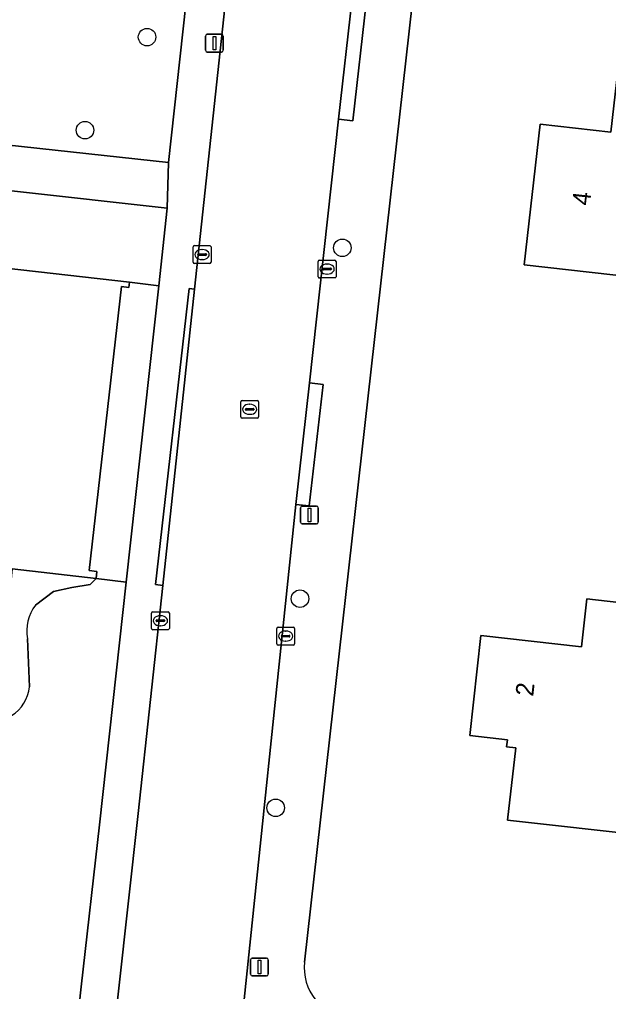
# Model space of a CAD drawing. Extents: x 162184 to 163154, y 385507 to 386516.
# Drawn here: x 162297.1 to 162330, y 385900.6 to 385954.9 of the extents above; entities that cross this region are included whole.
import ezdxf

# ---------------------------------------------------------------- set-up
doc = ezdxf.new("R2010")
doc.units = 0
for name, color, linetype in [('IMGEO_Boom', 7, 'Continuous'), ('IMGEO_Erf', 7, 'Continuous'), ('IMGEO_Groenvoorziening', 7, 'Continuous'), ('IMGEO_Kolk', 7, 'Continuous'), ('IMGEO_Lichtmast', 7, 'Continuous'), ('IMGEO_Pand', 7, 'Continuous'), ('IMGEO_Pand_nummerreeks', 7, 'Continuous'), ('IMGEO_Rijbaan_lokaal_open', 7, 'Continuous'), ('IMGEO_Rioolput', 7, 'Continuous'), ('IMGEO_Voetpad_open', 7, 'Continuous')]:
    doc.layers.add(name, color=color, linetype=linetype)

msp = doc.modelspace()

# ---------------------------------------------------------------- linework, layer by layer
at = {"layer": 'IMGEO_Boom'}
for centre in [(162304.242, 385953.933), (162300.775, 385948.732), (162315.151, 385942.163), (162312.782, 385922.559), (162311.424, 385910.875)]:
    msp.add_circle(centre, 0.489, dxfattribs=at)
at = {"layer": 'IMGEO_Erf'}
msp.add_lwpolyline([(162328.975, 386043.984), (162324.028, 386000), (162313.036, 385902.247)], dxfattribs=at)
for points in [[(162341.386, 385949.331), (162336.906, 385949.839), (162336.451, 385945.838), (162335.79, 385940.016), (162330.265, 385940.644), (162325.296, 385941.208), (162326.189, 385949.065), (162330.142, 385948.616), (162330.792, 385954.341), (162335.761, 385953.777), (162341.813, 385953.089)], [(162338.284, 385931.993), (162337.602, 385925.852), (162334.596, 385926.197), (162333.253, 385914.201), (162332.776, 385914.255), (162332.223, 385909.314), (162324.378, 385910.191), (162324.83, 385914.225), (162324.326, 385914.281), (162324.371, 385914.682), (162322.264, 385914.918), (162322.889, 385920.507), (162328.511, 385919.878), (162328.809, 385922.544), (162330.592, 385922.345), (162331.798, 385932.685)]]:
    msp.add_lwpolyline(points, close=True, dxfattribs=at)
msp.add_arc((162315.865, 385901.93), 2.846, 173.6034, 263.6318, dxfattribs=at)
at = {"layer": 'IMGEO_Groenvoorziening'}
for points in [[(162287.293, 385948.899), (162305.445, 385946.92), (162308.336, 385973.43)], [(162298.011, 385922.193), (162299.009, 385922.952), (162300.039, 385923.181), (162301.055, 385923.347), (162301.395, 385923.695), (162296.7, 385924.228), (162296.135, 385918.103), (162285.746, 385919.171), (162281.216, 385919.685), (162280.994, 385917.729), (162283.394, 385917.48), (162284.595, 385917.841), (162286.256, 385917.978), (162288.664, 385917.633), (162290.709, 385917.246), (162292.811, 385916.527), (162294.784, 385915.888)], [(162301.577, 385909.923), (162303.065, 385923.488), (162301.395, 385923.695), (162301.055, 385923.347), (162300.039, 385923.181), (162299.009, 385922.952), (162298.011, 385922.193)], [(162297.666, 385917.642), (162297.57, 385920.323)], [(162297.57, 385920.323), (162297.666, 385917.642)], [(162275.621, 385897.854), (162297.198, 385895.455), (162297.469, 385895.462), (162297.738, 385895.492), (162298.003, 385895.547), (162298.262, 385895.625), (162298.513, 385895.726), (162298.754, 385895.849), (162298.983, 385895.993), (162299.199, 385896.157), (162299.399, 385896.339), (162299.582, 385896.539), (162299.746, 385896.754), (162299.89, 385896.983), (162300.014, 385897.224), (162300.115, 385897.475), (162300.193, 385897.734), (162300.243, 385897.966), (162300.567, 385900.867), (162301.577, 385909.923)]]:
    msp.add_lwpolyline(points, dxfattribs=at)
msp.add_lwpolyline([(162296.364, 385941.021), (162303.254, 385940.239), (162304.896, 385940.036), (162305.369, 385944.374), (162288.289, 385946.274), (162287.788, 385941.99)], close=True, dxfattribs=at)
for centre, radius, start, end in [((162299.849, 385920.772), 2.323, 142.3043, 191.1566), ((162299.849, 385920.772), 2.323, 142.3043, 191.1566), ((162295.59, 385917.809), 2.083, 247.2373, 355.4125), ((162295.59, 385917.809), 2.083, 247.2373, 355.4125)]:
    msp.add_arc(centre, radius, start, end, dxfattribs=at)
at = {"layer": 'IMGEO_Kolk'}
for p, q in [((162306.813, 385941.356), (162306.813, 385942.208)), ((162306.888, 385942.282), (162307.74, 385942.282)), ((162307.301, 385942.062), (162307.326, 385942.062)), ((162307.814, 385942.208), (162307.814, 385941.356)), ((162307.072, 385941.776), (162307.072, 385941.788)), ((162307.51, 385941.739), (162307.112, 385941.739)), ((162307.115, 385941.825), (162307.513, 385941.825)), ((162307.324, 385941.502), (162307.299, 385941.502)), ((162307.556, 385941.788), (162307.556, 385941.776)), ((162313.87, 385941.475), (162314.722, 385941.475)), ((162307.74, 385941.282), (162306.888, 385941.282)), ((162313.795, 385940.549), (162313.795, 385941.401)), ((162314.054, 385940.969), (162314.054, 385940.981)), ((162314.492, 385940.932), (162314.094, 385940.932)), ((162314.097, 385941.018), (162314.495, 385941.018)), ((162314.283, 385941.255), (162314.308, 385941.255)), ((162314.538, 385940.981), (162314.538, 385940.969)), ((162314.796, 385941.401), (162314.796, 385940.549)), ((162314.722, 385940.475), (162313.87, 385940.475)), ((162314.306, 385940.695), (162314.281, 385940.695)), ((162304.485, 385920.902), (162304.485, 385921.754)), ((162304.56, 385921.828), (162305.412, 385921.828)), ((162304.744, 385921.322), (162304.744, 385921.334)), ((162304.787, 385921.371), (162305.185, 385921.371)), ((162304.973, 385921.608), (162304.998, 385921.608)), ((162305.228, 385921.334), (162305.228, 385921.322)), ((162305.486, 385921.754), (162305.486, 385920.902)), ((162305.412, 385920.828), (162304.56, 385920.828)), ((162305.182, 385921.285), (162304.784, 385921.285)), ((162304.996, 385921.048), (162304.971, 385921.048)), ((162311.48, 385920.041), (162311.48, 385920.893)), ((162311.555, 385920.967), (162312.407, 385920.967)), ((162312.481, 385920.893), (162312.481, 385920.041)), ((162311.739, 385920.461), (162311.739, 385920.473)), ((162312.177, 385920.424), (162311.779, 385920.424)), ((162311.782, 385920.51), (162312.18, 385920.51)), ((162311.968, 385920.747), (162311.993, 385920.747)), ((162312.223, 385920.473), (162312.223, 385920.461)), ((162312.407, 385919.967), (162311.555, 385919.967)), ((162311.991, 385920.187), (162311.966, 385920.187))]:
    msp.add_line(p, q, dxfattribs=at)
for points in [[(162306.813, 385941.356), (162306.813, 385942.208)], [(162306.888, 385942.282), (162307.74, 385942.282)], [(162307.814, 385942.208), (162307.814, 385941.356)], [(162313.87, 385941.475), (162314.722, 385941.475)], [(162307.74, 385941.282), (162306.888, 385941.282)], [(162313.795, 385940.549), (162313.795, 385941.401)], [(162314.796, 385941.401), (162314.796, 385940.549)], [(162314.722, 385940.475), (162313.87, 385940.475)], [(162304.485, 385920.902), (162304.485, 385921.754)], [(162304.56, 385921.828), (162305.412, 385921.828)], [(162305.486, 385921.754), (162305.486, 385920.902)], [(162305.412, 385920.828), (162304.56, 385920.828)], [(162311.48, 385920.041), (162311.48, 385920.893)], [(162311.555, 385920.967), (162312.407, 385920.967)], [(162312.481, 385920.893), (162312.481, 385920.041)], [(162312.407, 385919.967), (162311.555, 385919.967)]]:
    msp.add_lwpolyline(points, dxfattribs=at)
for centre, radius, start, end in [((162306.89, 385942.206), 0.0765, 91.552, 178.448), ((162306.89, 385942.206), 0.0765, 91.552, 178.448), ((162307.738, 385942.206), 0.0765, 1.552, 88.448), ((162307.738, 385942.206), 0.0765, 1.552, 88.448), ((162307.112, 385941.785), 0.0403, 85.8775, 175.7526), ((162307.109, 385941.775), 0.0366, 178.938, 274.7102), ((162307.513, 385941.782), 0.043, 264.8664, 352.4533), ((162307.517, 385941.787), 0.0386, 1.7309, 96.639), ((162313.872, 385941.399), 0.0765, 91.552, 178.448), ((162313.872, 385941.399), 0.0765, 91.552, 178.448), ((162314.72, 385941.399), 0.0765, 1.552, 88.448), ((162314.72, 385941.399), 0.0765, 1.552, 88.448), ((162306.89, 385941.358), 0.0765, 181.552, 268.448), ((162306.89, 385941.358), 0.0765, 181.552, 268.448), ((162307.738, 385941.358), 0.0765, 271.552, 358.448), ((162307.738, 385941.358), 0.0765, 271.552, 358.448), ((162314.094, 385940.978), 0.0403, 85.8775, 175.7526), ((162314.091, 385940.968), 0.0366, 178.938, 274.7102), ((162314.495, 385940.975), 0.043, 264.8664, 352.4533), ((162314.499, 385940.98), 0.0386, 1.7309, 96.639), ((162313.872, 385940.551), 0.0765, 181.552, 268.448), ((162313.872, 385940.551), 0.0765, 181.552, 268.448), ((162314.72, 385940.551), 0.0765, 271.552, 358.448), ((162314.72, 385940.551), 0.0765, 271.552, 358.448), ((162304.562, 385921.752), 0.0765, 91.552, 178.448), ((162304.562, 385921.752), 0.0765, 91.552, 178.448), ((162304.784, 385921.331), 0.0403, 85.8775, 175.7526), ((162305.189, 385921.333), 0.0386, 1.7309, 96.639), ((162305.41, 385921.752), 0.0765, 1.552, 88.448), ((162305.41, 385921.752), 0.0765, 1.552, 88.448), ((162304.562, 385920.904), 0.0765, 181.552, 268.448), ((162304.562, 385920.904), 0.0765, 181.552, 268.448), ((162304.781, 385921.321), 0.0366, 178.938, 274.7102), ((162305.185, 385921.328), 0.043, 264.8664, 352.4533), ((162305.41, 385920.904), 0.0765, 271.552, 358.448), ((162305.41, 385920.904), 0.0765, 271.552, 358.448), ((162311.557, 385920.891), 0.0765, 91.552, 178.448), ((162311.557, 385920.891), 0.0765, 91.552, 178.448), ((162312.405, 385920.891), 0.0765, 1.552, 88.448), ((162312.405, 385920.891), 0.0765, 1.552, 88.448), ((162311.779, 385920.47), 0.0403, 85.8775, 175.7526), ((162311.776, 385920.46), 0.0366, 178.938, 274.7102), ((162312.18, 385920.467), 0.043, 264.8664, 352.4533), ((162312.184, 385920.472), 0.0386, 1.7309, 96.639), ((162311.557, 385920.043), 0.0765, 181.552, 268.448), ((162311.557, 385920.043), 0.0765, 181.552, 268.448), ((162312.405, 385920.043), 0.0765, 271.552, 358.448), ((162312.405, 385920.043), 0.0765, 271.552, 358.448)]:
    msp.add_arc(centre, radius, start, end, dxfattribs=at)
for centre, major_axis, ratio, start_param, end_param in [((162307.3, 385941.782), (-0.387, 0.002), 0.722429, 4.712389, 7.853982), ((162307.325, 385941.782), (-0.39, 0.002), 0.717154, 1.570796, 4.712389), ((162314.282, 385940.975), (-0.387, 0.002), 0.722429, 4.712389, 7.853982), ((162314.307, 385940.975), (-0.39, 0.002), 0.717154, 1.570796, 4.712389), ((162304.972, 385921.328), (-0.387, 0.002), 0.722429, 4.712389, 7.853982), ((162304.997, 385921.328), (-0.39, 0.002), 0.717154, 1.570796, 4.712389), ((162311.967, 385920.467), (-0.387, 0.002), 0.722429, 4.712389, 7.853982), ((162311.992, 385920.467), (-0.39, 0.002), 0.717154, 1.570796, 4.712389)]:
    msp.add_ellipse(centre, major_axis=major_axis, ratio=ratio, start_param=start_param, end_param=end_param, dxfattribs=at)
at = {"layer": 'IMGEO_Lichtmast'}
for p, q in [((162307.506, 385953.194), (162307.506, 385953.994)), ((162307.506, 385953.994), (162307.506, 385953.194)), ((162307.606, 385954.094), (162308.396, 385954.094)), ((162308.396, 385954.094), (162307.606, 385954.094)), ((162308.496, 385953.994), (162308.496, 385953.194)), ((162308.496, 385953.194), (162308.496, 385953.994)), ((162308.396, 385953.094), (162307.606, 385953.094)), ((162307.606, 385953.094), (162308.396, 385953.094)), ((162312.81, 385926.833), (162312.81, 385927.633)), ((162312.81, 385927.633), (162312.81, 385926.833)), ((162312.91, 385927.733), (162313.7, 385927.733)), ((162313.7, 385927.733), (162312.91, 385927.733)), ((162313.8, 385927.633), (162313.8, 385926.833)), ((162313.8, 385926.833), (162313.8, 385927.633)), ((162313.7, 385926.733), (162312.91, 385926.733)), ((162312.91, 385926.733), (162313.7, 385926.733)), ((162310.019, 385901.583), (162310.019, 385902.383)), ((162310.019, 385902.383), (162310.019, 385901.583)), ((162310.119, 385902.483), (162310.909, 385902.483)), ((162310.909, 385902.483), (162310.119, 385902.483)), ((162311.009, 385902.383), (162311.009, 385901.583)), ((162311.009, 385901.583), (162311.009, 385902.383)), ((162310.909, 385901.483), (162310.119, 385901.483)), ((162310.119, 385901.483), (162310.909, 385901.483))]:
    msp.add_line(p, q, dxfattribs=at)
for points in [[(162307.926, 385953.969), (162308.076, 385953.969), (162308.076, 385953.219), (162307.926, 385953.219), (162307.926, 385953.969)], [(162313.23, 385927.608), (162313.38, 385927.608), (162313.38, 385926.858), (162313.23, 385926.858), (162313.23, 385927.608)], [(162310.439, 385902.358), (162310.589, 385902.358), (162310.589, 385901.608), (162310.439, 385901.608), (162310.439, 385902.358)]]:
    msp.add_lwpolyline(points, dxfattribs=at)
for centre, start, end in [((162307.606, 385953.994), 90, 180), ((162307.606, 385953.994), 90, 180), ((162308.396, 385953.994), 0, 90), ((162308.396, 385953.994), 360, 90), ((162307.606, 385953.194), 180, 270), ((162307.606, 385953.194), 180, 270), ((162308.396, 385953.194), 270, 0), ((162308.396, 385953.194), 270, 0), ((162312.91, 385927.633), 90, 180), ((162312.91, 385927.633), 90, 180), ((162313.7, 385927.633), 0, 90), ((162313.7, 385927.633), 360, 90), ((162312.91, 385926.833), 180, 270), ((162312.91, 385926.833), 180, 270), ((162313.7, 385926.833), 270, 0), ((162313.7, 385926.833), 270, 0), ((162310.119, 385902.383), 90, 180), ((162310.119, 385902.383), 90, 180), ((162310.909, 385902.383), 0, 90), ((162310.909, 385902.383), 360, 90), ((162310.119, 385901.583), 180, 270), ((162310.119, 385901.583), 180, 270), ((162310.909, 385901.583), 270, 0), ((162310.909, 385901.583), 270, 0)]:
    msp.add_arc(centre, 0.1, start, end, dxfattribs=at)
at = {"layer": 'IMGEO_Pand'}
for points in [[(162336.906, 385949.839), (162341.386, 385949.331), (162341.813, 385953.089), (162335.761, 385953.777), (162330.792, 385954.341), (162330.142, 385948.616), (162326.189, 385949.065), (162325.296, 385941.208), (162330.265, 385940.644), (162335.79, 385940.016), (162336.451, 385945.838)], [(162296.364, 385941.021), (162296.04, 385938.627), (162295.384, 385932.873), (162294.432, 385924.485), (162296.7, 385924.228), (162301.395, 385923.695), (162301.439, 385924.078), (162301.007, 385924.127), (162302.808, 385939.999), (162303.221, 385939.952), (162303.254, 385940.239)], [(162334.596, 385926.197), (162337.602, 385925.852), (162338.284, 385931.993), (162331.798, 385932.685), (162330.592, 385922.345), (162328.809, 385922.544), (162328.511, 385919.878), (162322.889, 385920.507), (162322.264, 385914.918), (162324.371, 385914.682), (162324.326, 385914.281), (162324.83, 385914.225), (162324.378, 385910.191), (162332.223, 385909.314), (162332.776, 385914.255), (162333.253, 385914.201)]]:
    msp.add_lwpolyline(points, close=True, dxfattribs=at)
at = {"layer": 'IMGEO_Rijbaan_lokaal_open'}
msp.add_lwpolyline([(162311.186, 385979.821), (162306.893, 385939.847), (162305.116, 385923.293), (162303.749, 385910.566), (162302.645, 385900.63), (162302.442, 385898.8), (162309.432, 385898.029), (162312.557, 385927.828), (162313.306, 385934.616), (162314.938, 385949.347), (162315.696, 385956.099)], dxfattribs=at)
at = {"layer": 'IMGEO_Rioolput'}
for p, q in [((162309.471, 385932.712), (162309.471, 385933.564)), ((162309.546, 385933.638), (162310.398, 385933.638)), ((162309.959, 385933.418), (162309.984, 385933.418)), ((162310.472, 385933.564), (162310.472, 385932.712)), ((162309.73, 385933.132), (162309.73, 385933.144)), ((162310.168, 385933.095), (162309.77, 385933.095)), ((162309.773, 385933.181), (162310.171, 385933.181)), ((162309.982, 385932.858), (162309.957, 385932.858)), ((162310.214, 385933.144), (162310.214, 385933.132)), ((162310.398, 385932.638), (162309.546, 385932.638))]:
    msp.add_line(p, q, dxfattribs=at)
for points in [[(162309.471, 385932.712), (162309.471, 385933.564)], [(162309.546, 385933.638), (162310.398, 385933.638)], [(162310.472, 385933.564), (162310.472, 385932.712)], [(162310.398, 385932.638), (162309.546, 385932.638)]]:
    msp.add_lwpolyline(points, dxfattribs=at)
for centre, radius, start, end in [((162309.548, 385933.562), 0.0765, 91.552, 178.448), ((162309.548, 385933.562), 0.0765, 91.552, 178.448), ((162310.396, 385933.562), 0.0765, 1.552, 88.448), ((162310.396, 385933.562), 0.0765, 1.552, 88.448), ((162309.77, 385933.141), 0.0403, 85.8775, 175.7526), ((162309.767, 385933.131), 0.0366, 178.938, 274.7102), ((162310.171, 385933.138), 0.043, 264.8664, 352.4533), ((162310.175, 385933.143), 0.0386, 1.7309, 96.639), ((162309.548, 385932.714), 0.0765, 181.552, 268.448), ((162309.548, 385932.714), 0.0765, 181.552, 268.448), ((162310.396, 385932.714), 0.0765, 271.552, 358.448), ((162310.396, 385932.714), 0.0765, 271.552, 358.448)]:
    msp.add_arc(centre, radius, start, end, dxfattribs=at)
for centre, major_axis, ratio, start_param, end_param in [((162309.958, 385933.138), (-0.387, 0.002), 0.722429, 4.712389, 7.853982), ((162309.983, 385933.138), (-0.39, 0.002), 0.717154, 1.570796, 4.712389)]:
    msp.add_ellipse(centre, major_axis=major_axis, ratio=ratio, start_param=start_param, end_param=end_param, dxfattribs=at)
at = {"layer": 'IMGEO_Voetpad_open'}
for points in [[(162302.442, 385898.8), (162302.645, 385900.63), (162303.749, 385910.566), (162305.116, 385923.293), (162304.706, 385923.345), (162306.596, 385939.881), (162306.893, 385939.847), (162311.186, 385979.821), (162313.075, 385996.531), (162314.97, 386013.433), (162317.601, 386036.567), (162318.762, 386046.916), (162318.885, 386047.742), (162319.138, 386048.845), (162319.488, 386049.922), (162319.933, 386050.963), (162320.47, 386051.961), (162321.093, 386052.906)], [(162325.667, 386043.936), (162322.638, 386017.967), (162323.428, 386017.878), (162322.889, 386013.064), (162322.098, 386013.153), (162320.347, 385997.546), (162321.149, 385997.456), (162320.72, 385993.607), (162319.915, 385993.698), (162318.116, 385977.668), (162318.915, 385977.577), (162318.488, 385973.802), (162317.692, 385973.893), (162315.696, 385956.099), (162316.488, 385956.004), (162315.731, 385949.252), (162314.938, 385949.347), (162313.306, 385934.616), (162314.069, 385934.525), (162313.303, 385927.738), (162312.557, 385927.828), (162309.432, 385898.029), (162315.549, 385899.101)], [(162313.036, 385902.247), (162324.028, 386000)], [(162308.336, 385973.43), (162305.445, 385946.92), (162305.369, 385944.374), (162304.896, 385940.036), (162303.065, 385923.488), (162301.577, 385909.923), (162300.567, 385900.867), (162300.243, 385897.966), (162300.193, 385897.734), (162300.115, 385897.475), (162300.014, 385897.224), (162299.89, 385896.983), (162299.746, 385896.754), (162299.582, 385896.539), (162299.399, 385896.339), (162299.199, 385896.157), (162298.983, 385895.993), (162298.754, 385895.849), (162298.513, 385895.726), (162298.262, 385895.625), (162298.003, 385895.547), (162300.34, 385894.856)], [(162288.289, 385946.274), (162305.369, 385944.374), (162305.445, 385946.92), (162287.293, 385948.899)]]:
    msp.add_lwpolyline(points, dxfattribs=at)
for points in [[(162316.488, 385956.004), (162315.696, 385956.099), (162314.938, 385949.347), (162315.731, 385949.252)], [(162303.065, 385923.488), (162304.896, 385940.036), (162303.254, 385940.239), (162303.221, 385939.952), (162302.808, 385939.999), (162301.007, 385924.127), (162301.439, 385924.078), (162301.395, 385923.695)], [(162306.893, 385939.847), (162306.596, 385939.881), (162304.706, 385923.345), (162305.116, 385923.293)], [(162314.069, 385934.525), (162313.306, 385934.616), (162312.557, 385927.828), (162313.303, 385927.738)]]:
    msp.add_lwpolyline(points, close=True, dxfattribs=at)
msp.add_arc((162315.865, 385901.93), 2.846, 173.6034, 263.6318, dxfattribs=at)

# ---------------------------------------------------------------- texts
at = {"layer": 'IMGEO_Pand_nummerreeks'}
for s, rotation, p in [('4', 83.5158, (162328.971, 385944.492)), ('2', 83.6175, (162325.806, 385917.072))]:
    msp.add_text(s, height=1, rotation=rotation, dxfattribs=at).set_placement(p)

doc.saveas('drawing.dxf')
